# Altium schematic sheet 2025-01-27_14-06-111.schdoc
size 303 x 115 mm; SheetNumber: 1; SheetTotal: 1
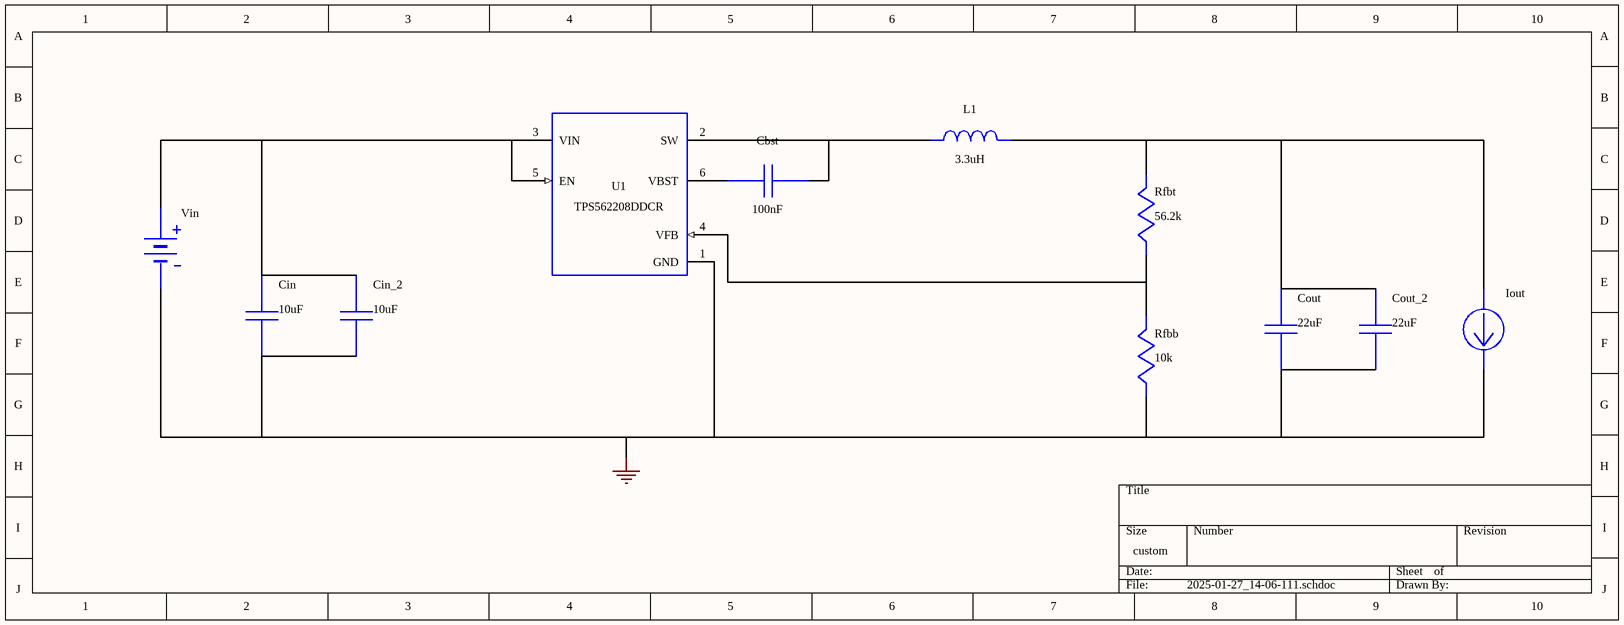
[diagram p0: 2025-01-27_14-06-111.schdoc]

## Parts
Cbst  value 100nF  (hidden comment: 08053C104KAT2A)
Cin  value 10uF  (hidden comment: C2012X5R1V106K085AC)
Cin_2  value 10uF  (hidden comment: C2012X5R1V106K085AC)
Cout  value 22uF  (hidden comment: C1608X5R1A226M080AC)
Cout_2  value 22uF  (hidden comment: C1608X5R1A226M080AC)
Iout  WB_CURRENT_LOAD  (value not drawn)
L1  value 3.3uH  (hidden comment: VLP8040T-3R3N)
Rfbb  value 10k  (hidden comment: RC0201FR-0710KL)
Rfbt  value 56.2k  (hidden comment: RC0201FR-0756K2L)
U1  TPS562208DDCR
Vin  WB_BATTERY  (value not drawn)

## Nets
0: Cin.2 Cin_2.2 Cout.2 Cout_2.2 Iout.2(-) Rfbb.2 U1.1(GND) Vin.2(-)
NetCbst_1: Cbst.1 L1.1 U1.2(SW)
NetCbst_2: Cbst.2 U1.6(VBST)
NetCin_1: Cin.1 Cin_2.1 U1.3(VIN) U1.5(EN) Vin.1(+)
NetCout_1: Cout.1 Cout_2.1 Iout.1(+) L1.2 Rfbt.1
NetRfbb_1: Rfbb.1 Rfbt.2 U1.4(VFB)

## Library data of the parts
Cbst = 08053C104KAT2A: Manufacturer Name: AVX
Cin Cin_2 = C2012X5R1V106K085AC: C2012X5R1V106K08; Manufacturer Name: TDK
Cout Cout_2 = C1608X5R1A226M080AC: C1608X5R1A226M08; Manufacturer Name: TDK
L1 = VLP8040T-3R3N: Unknown; Manufacturer Name: TDK
Rfbb = RC0201FR-0710KL: Manufacturer Name: Yageo
Rfbt = RC0201FR-0756K2L: Manufacturer Name: Yageo
U1 = TPS562208DDCR: Manufacturer Name: Texas Instruments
